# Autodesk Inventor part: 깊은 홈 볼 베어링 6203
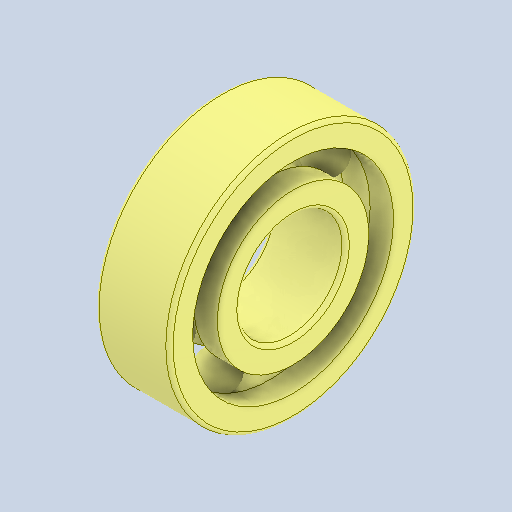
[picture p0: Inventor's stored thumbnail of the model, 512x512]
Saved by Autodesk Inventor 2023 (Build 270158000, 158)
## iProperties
Created: 2025-04
Part Number: 깊은 홈 볼 베어링 6203
Material: 강철, 연강
Description: 깊은 그루브 볼 베어링
Document SubType Name: Modeling
Designer: ADMIN_PC
Density: 7.86 g/cm^3
Appearance: 기본값
Author: jhkim
Revision Number: 1
Sending System: Autodesk Inventor 2026
Preprocessor: ST-DEVELOPER v20.1
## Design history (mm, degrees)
feature "Solid1"
feature "Solid1:1"
feature "Solid1:2"
feature "Solid1:3"
feature "Solid1:4"
feature "Solid1:5"
feature "Solid1:6"
feature "Solid1:7"
feature "Solid1:8"
node "솔리드1"
node "솔리드2"
node "솔리드3"
node "솔리드4"
node "솔리드5"
node "솔리드6"
node "솔리드7"
node "솔리드8"
node "솔리드9"
